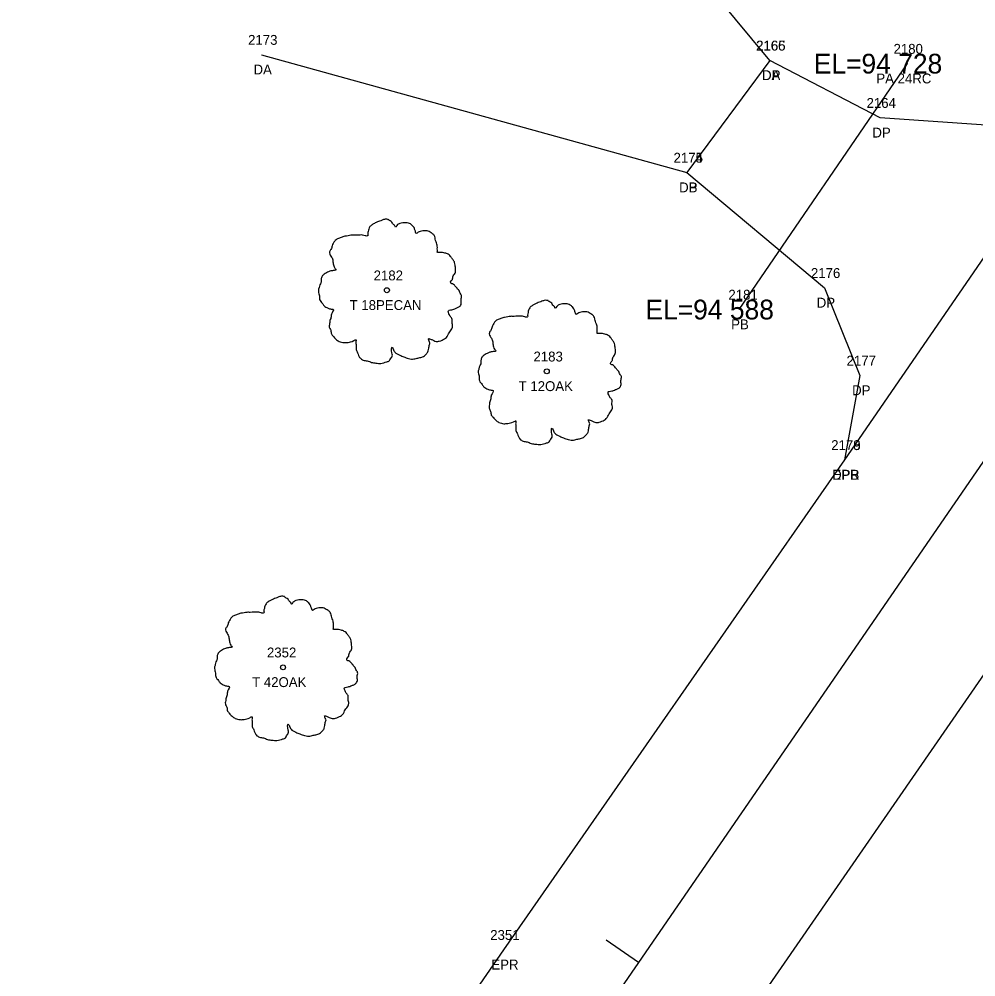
# Model space of a CAD drawing. Extents: x 2266664 to 2272542, y 716533 to 724777.
# Drawn here: x 2271769.3 to 2271866.2, y 723993.3 to 724090.3 of the extents above; entities that cross this region are included whole.
import ezdxf

# ---------------------------------------------------------------- set-up
doc = ezdxf.new("R2010")
doc.units = 0
for name, color, linetype in [('RD_EX_DR_Pipe', 7, 'Continuous'), ('RD_EX_DR_Pipe_txCode', 7, 'Continuous'), ('RD_EX_Driveway', 7, 'Continuous'), ('RD_EX_Driveway_txCode', 7, 'Continuous'), ('RD_EX_Road', 7, 'Continuous'), ('RD_EX_Road_txCode', 7, 'Continuous'), ('RD_EX_VEG', 7, 'Continuous'), ('RD_EX_VEG_txCode', 7, 'Continuous'), ('RD_HC_Cl', 7, 'Continuous'), ('RD_HC_Data_Tic', 7, 'Continuous'), ('RD_SMD_Locator', 7, 'Continuous'), ('RD_TX_Pipe_ElevEX', 7, 'Continuous')]:
    doc.layers.add(name, color=color, linetype=linetype)

msp = doc.modelspace()

# ---------------------------------------------------------------- linework, layer by layer
at = {"layer": 'RD_EX_DR_Pipe'}
msp.add_line((2271859.252, 724085.767), (2271842.205, 724060.863), dxfattribs=at)
at = {"layer": 'RD_EX_Driveway'}
for p, q in [((2271845.335, 724086.097), (2271819.867, 724116.758)), ((2271793.852, 724086.675), (2271836.935, 724074.737))]:
    msp.add_line(p, q, dxfattribs=at)
msp.add_lwpolyline([(2271879.395, 724084.162), (2271867.735, 724079.491), (2271856.504, 724080.286), (2271845.335, 724086.097), (2271836.935, 724074.737), (2271850.87, 724063.059), (2271854.455, 724054.184), (2271852.899, 724045.631)], dxfattribs=at)
at = {"layer": 'RD_EX_Road'}
for points in [[(2272350.524, 724770.05), (2272301.752, 724698.898), (2272265.201, 724646.018), (2272253.016, 724627.92), (2272200.511, 724550.874), (2272147.542, 724474.345), (2272126.282, 724443.661), (2272107.363, 724416.481), (2272092.202, 724393.687), (2272038.416, 724315.204), (2271991.524, 724247.474), (2271974.411, 724222.156), (2271928.733, 724155.869), (2271879.395, 724084.162), (2271852.899, 724045.631), (2271818.371, 723996.017), (2271765.116, 723918.771), (2271712.349, 723841.582), (2271659.046, 723763.608), (2271604.53, 723684.774), (2271550.651, 723606.609)], [(2272368.973, 724754.134), (2272346.573, 724721.921), (2272321.774, 724685.095), (2272273.252, 724614.425), (2272223.015, 724540.912), (2272206.831, 724517.638), (2272178.601, 724477.026), (2272166.485, 724459.37), (2272137.666, 724416.893), (2272108.529, 724374.933), (2272057.894, 724300.992), (2272036.237, 724269.85), (2272022.133, 724249.172), (2272003.164, 724221.268), (2271948.474, 724142.381), (2271900.702, 724072.985), (2271873.703, 724033.584), (2271837.938, 723981.874), (2271784.957, 723904.948), (2271732.121, 723828.062), (2271678.324, 723749.568), (2271627.924, 723676.616), (2271614.207, 723655.348), (2271570.616, 723593.072)]]:
    msp.add_lwpolyline(points, dxfattribs=at)
at = {"layer": 'RD_EX_VEG'}
for centre, radius in [((2271806.565, 724062.817), 0.25), ((2271806.552, 724062.798), 0.0001), ((2271822.751, 724054.604), 0.25), ((2271822.739, 724054.586), 0.0001), ((2271796.045, 724024.628), 0.25), ((2271796.032, 724024.609), 0.0001)]:
    msp.add_circle(centre, radius, dxfattribs=at)
for points in [[(2271806.697, 724069.984), (2271806.397, 724070.009), (2271806.072, 724069.909), (2271805.822, 724069.809), (2271805.597, 724069.734), (2271805.373, 724069.634), (2271805.073, 724069.459), (2271804.848, 724069.259), (2271804.723, 724069.009), (2271804.673, 724068.784), (2271804.623, 724068.51), (2271804.623, 724068.335), (2271804.498, 724068.31), (2271804.348, 724068.335), (2271804.098, 724068.41), (2271803.848, 724068.41), (2271803.598, 724068.41), (2271803.248, 724068.385), (2271802.899, 724068.385), (2271802.624, 724068.335), (2271802.299, 724068.285), (2271801.924, 724068.16), (2271801.574, 724068.035), (2271801.274, 724067.785), (2271801.024, 724067.31), (2271800.899, 724066.96), (2271800.75, 724066.71), (2271800.899, 724066.261), (2271801.074, 724065.911), (2271801.099, 724065.711), (2271801.174, 724065.286), (2271801.274, 724065.061), (2271801.399, 724064.861), (2271801.324, 724064.836), (2271800.949, 724064.786), (2271800.65, 724064.686), (2271800.225, 724064.461), (2271800, 724064.236), (2271799.9, 724063.912), (2271799.875, 724063.562), (2271799.775, 724063.362), (2271799.7, 724063.087), (2271799.675, 724063.012), (2271799.625, 724062.687), (2271799.725, 724062.237), (2271799.75, 724061.887), (2271799.875, 724061.663), (2271800.025, 724061.488), (2271800.2, 724061.238), (2271800.6, 724061.013), (2271800.924, 724060.913), (2271801.124, 724060.888), (2271800.949, 724060.388), (2271800.899, 724060.038), (2271800.775, 724059.638), (2271800.775, 724059.564), (2271800.725, 724059.089), (2271800.874, 724058.764), (2271800.949, 724058.389), (2271801.124, 724058.164), (2271801.399, 724057.864), (2271801.724, 724057.639), (2271802.224, 724057.514), (2271802.624, 724057.539), (2271803.199, 724057.714), (2271803.448, 724057.789), (2271803.423, 724057.614), (2271803.448, 724057.239), (2271803.448, 724056.815), (2271803.598, 724056.49), (2271803.698, 724056.215), (2271803.848, 724055.965), (2271804.173, 724055.74), (2271804.573, 724055.665), (2271804.998, 724055.515), (2271805.448, 724055.44), (2271805.947, 724055.415), (2271806.547, 724055.565), (2271806.822, 724055.69), (2271806.922, 724055.865), (2271807.122, 724056.24), (2271807.072, 724056.465), (2271807.097, 724057.065), (2271807.197, 724056.89), (2271807.372, 724056.54), (2271807.871, 724056.24), (2271808.271, 724056.065), (2271808.746, 724055.915), (2271809.046, 724055.84), (2271809.521, 724055.915), (2271809.896, 724055.99), (2271810.27, 724056.115), (2271810.57, 724056.39), (2271810.745, 724056.665), (2271810.795, 724056.94), (2271810.87, 724057.314), (2271810.92, 724057.489)], [(2271810.92, 724057.489), (2271810.845, 724057.664), (2271810.795, 724057.914), (2271810.87, 724057.889), (2271811.045, 724057.839), (2271811.32, 724057.714), (2271811.545, 724057.639), (2271811.87, 724057.664), (2271812.145, 724057.764), (2271812.594, 724058.039), (2271812.869, 724058.514), (2271813.144, 724058.914), (2271813.219, 724059.239), (2271813.169, 724059.464), (2271813.144, 724059.963), (2271812.944, 724060.213), (2271812.894, 724060.338), (2271812.794, 724060.738), (2271812.869, 724060.788), (2271813.144, 724060.838), (2271813.519, 724060.963), (2271813.794, 724061.088), (2271814.019, 724061.263), (2271814.094, 724061.488), (2271814.069, 724061.887), (2271814.119, 724062.287), (2271814.044, 724062.437), (2271813.944, 724062.587), (2271813.869, 724062.787), (2271813.719, 724062.937), (2271813.619, 724063.087), (2271813.519, 724063.187), (2271813.394, 724063.337), (2271813.219, 724063.462), (2271813.069, 724063.512), (2271813.019, 724063.662), (2271813.169, 724063.862), (2271813.219, 724063.962), (2271813.244, 724064.186), (2271813.469, 724064.536), (2271813.519, 724064.936), (2271813.469, 724065.361), (2271813.419, 724065.636), (2271813.269, 724065.911), (2271813.069, 724066.161), (2271812.944, 724066.336), (2271812.769, 724066.46), (2271812.444, 724066.585), (2271812.195, 724066.635), (2271811.845, 724066.635), (2271811.645, 724066.685), (2271811.67, 724066.735), (2271811.67, 724066.885), (2271811.67, 724067.16), (2271811.595, 724067.61), (2271811.445, 724068.11), (2271811.445, 724068.135), (2271811.345, 724068.385), (2271811.12, 724068.585), (2271810.945, 724068.684), (2271810.745, 724068.809), (2271810.495, 724068.834), (2271810.195, 724068.834), (2271809.921, 724068.784), (2271809.721, 724068.684), (2271809.546, 724068.56), (2271809.471, 724068.709), (2271809.371, 724069.009), (2271809.321, 724069.159), (2271809.171, 724069.334), (2271808.946, 724069.534), (2271808.496, 724069.659), (2271807.871, 724069.584), (2271807.572, 724069.384), (2271807.422, 724069.209), (2271807.372, 724069.334), (2271807.172, 724069.534), (2271807.072, 724069.709), (2271806.897, 724069.834), (2271806.747, 724069.934), (2271806.647, 724069.984)], [(2271822.883, 724061.772), (2271822.583, 724061.797), (2271822.259, 724061.697), (2271822.009, 724061.597), (2271821.784, 724061.522), (2271821.559, 724061.422), (2271821.259, 724061.247), (2271821.034, 724061.047), (2271820.909, 724060.797), (2271820.859, 724060.572), (2271820.809, 724060.297), (2271820.809, 724060.122), (2271820.684, 724060.097), (2271820.534, 724060.122), (2271820.284, 724060.197), (2271820.035, 724060.197), (2271819.785, 724060.197), (2271819.435, 724060.172), (2271819.085, 724060.172), (2271818.81, 724060.122), (2271818.485, 724060.072), (2271818.11, 724059.947), (2271817.761, 724059.822), (2271817.461, 724059.573), (2271817.211, 724059.098), (2271817.086, 724058.748), (2271816.936, 724058.498), (2271817.086, 724058.048), (2271817.261, 724057.698), (2271817.286, 724057.498), (2271817.361, 724057.074), (2271817.461, 724056.849), (2271817.586, 724056.649), (2271817.511, 724056.624), (2271817.136, 724056.574), (2271816.836, 724056.474), (2271816.411, 724056.249), (2271816.186, 724056.024), (2271816.086, 724055.699), (2271816.061, 724055.349), (2271815.961, 724055.15), (2271815.886, 724054.875), (2271815.861, 724054.8), (2271815.811, 724054.475), (2271815.911, 724054.025), (2271815.936, 724053.675), (2271816.061, 724053.45), (2271816.211, 724053.275), (2271816.386, 724053.025), (2271816.786, 724052.801), (2271817.111, 724052.701), (2271817.311, 724052.676), (2271817.136, 724052.176), (2271817.086, 724051.826), (2271816.961, 724051.426), (2271816.961, 724051.351), (2271816.911, 724050.876), (2271817.061, 724050.551), (2271817.136, 724050.177), (2271817.311, 724049.952), (2271817.586, 724049.652), (2271817.91, 724049.427), (2271818.41, 724049.302), (2271818.81, 724049.327), (2271819.385, 724049.502), (2271819.635, 724049.577), (2271819.61, 724049.402), (2271819.635, 724049.027), (2271819.635, 724048.602), (2271819.785, 724048.278), (2271819.885, 724048.003), (2271820.035, 724047.753), (2271820.359, 724047.528), (2271820.759, 724047.453), (2271821.184, 724047.303), (2271821.634, 724047.228), (2271822.134, 724047.203), (2271822.733, 724047.353), (2271823.008, 724047.478), (2271823.108, 724047.653), (2271823.308, 724048.028), (2271823.258, 724048.253), (2271823.283, 724048.852), (2271823.383, 724048.677), (2271823.558, 724048.327), (2271824.058, 724048.028), (2271824.458, 724047.853), (2271824.932, 724047.703), (2271825.232, 724047.628), (2271825.707, 724047.703), (2271826.082, 724047.778), (2271826.457, 724047.903), (2271826.757, 724048.178), (2271826.932, 724048.452), (2271826.982, 724048.727), (2271827.056, 724049.102), (2271827.106, 724049.277)], [(2271827.106, 724049.277), (2271827.032, 724049.452), (2271826.982, 724049.702), (2271827.056, 724049.677), (2271827.231, 724049.627), (2271827.506, 724049.502), (2271827.731, 724049.427), (2271828.056, 724049.452), (2271828.331, 724049.552), (2271828.781, 724049.827), (2271829.056, 724050.302), (2271829.33, 724050.701), (2271829.405, 724051.026), (2271829.355, 724051.251), (2271829.33, 724051.751), (2271829.131, 724052.001), (2271829.081, 724052.126), (2271828.981, 724052.526), (2271829.056, 724052.576), (2271829.33, 724052.626), (2271829.705, 724052.751), (2271829.98, 724052.875), (2271830.205, 724053.05), (2271830.28, 724053.275), (2271830.255, 724053.675), (2271830.305, 724054.075), (2271830.23, 724054.225), (2271830.13, 724054.375), (2271830.055, 724054.575), (2271829.905, 724054.725), (2271829.805, 724054.875), (2271829.705, 724054.975), (2271829.58, 724055.125), (2271829.405, 724055.249), (2271829.256, 724055.299), (2271829.206, 724055.449), (2271829.355, 724055.649), (2271829.405, 724055.749), (2271829.43, 724055.974), (2271829.655, 724056.324), (2271829.705, 724056.724), (2271829.655, 724057.149), (2271829.605, 724057.424), (2271829.455, 724057.698), (2271829.256, 724057.948), (2271829.131, 724058.123), (2271828.956, 724058.248), (2271828.631, 724058.373), (2271828.381, 724058.423), (2271828.031, 724058.423), (2271827.831, 724058.473), (2271827.856, 724058.523), (2271827.856, 724058.673), (2271827.856, 724058.948), (2271827.781, 724059.398), (2271827.631, 724059.897), (2271827.631, 724059.922), (2271827.531, 724060.172), (2271827.306, 724060.372), (2271827.131, 724060.472), (2271826.932, 724060.597), (2271826.682, 724060.622), (2271826.382, 724060.622), (2271826.107, 724060.572), (2271825.907, 724060.472), (2271825.732, 724060.347), (2271825.657, 724060.497), (2271825.557, 724060.797), (2271825.507, 724060.947), (2271825.357, 724061.122), (2271825.132, 724061.322), (2271824.682, 724061.447), (2271824.058, 724061.372), (2271823.758, 724061.172), (2271823.608, 724060.997), (2271823.558, 724061.122), (2271823.358, 724061.322), (2271823.258, 724061.497), (2271823.083, 724061.622), (2271822.933, 724061.722), (2271822.833, 724061.772)], [(2271796.177, 724031.795), (2271795.877, 724031.82), (2271795.552, 724031.72), (2271795.302, 724031.62), (2271795.077, 724031.545), (2271794.852, 724031.445), (2271794.552, 724031.27), (2271794.327, 724031.07), (2271794.202, 724030.82), (2271794.152, 724030.595), (2271794.102, 724030.32), (2271794.102, 724030.145), (2271793.978, 724030.12), (2271793.828, 724030.145), (2271793.578, 724030.22), (2271793.328, 724030.22), (2271793.078, 724030.22), (2271792.728, 724030.195), (2271792.378, 724030.195), (2271792.103, 724030.145), (2271791.778, 724030.096), (2271791.404, 724029.971), (2271791.054, 724029.846), (2271790.754, 724029.596), (2271790.504, 724029.121), (2271790.379, 724028.771), (2271790.229, 724028.521), (2271790.379, 724028.071), (2271790.554, 724027.722), (2271790.579, 724027.522), (2271790.654, 724027.097), (2271790.754, 724026.872), (2271790.879, 724026.672), (2271790.804, 724026.647), (2271790.429, 724026.597), (2271790.129, 724026.497), (2271789.704, 724026.272), (2271789.479, 724026.047), (2271789.379, 724025.722), (2271789.355, 724025.373), (2271789.255, 724025.173), (2271789.18, 724024.898), (2271789.155, 724024.823), (2271789.105, 724024.498), (2271789.205, 724024.048), (2271789.23, 724023.698), (2271789.355, 724023.473), (2271789.504, 724023.299), (2271789.679, 724023.049), (2271790.079, 724022.824), (2271790.404, 724022.724), (2271790.604, 724022.699), (2271790.429, 724022.199), (2271790.379, 724021.849), (2271790.254, 724021.449), (2271790.254, 724021.374), (2271790.204, 724020.9), (2271790.354, 724020.575), (2271790.429, 724020.2), (2271790.604, 724019.975), (2271790.879, 724019.675), (2271791.204, 724019.45), (2271791.704, 724019.325), (2271792.103, 724019.35), (2271792.678, 724019.525), (2271792.928, 724019.6), (2271792.903, 724019.425), (2271792.928, 724019.05), (2271792.928, 724018.626), (2271793.078, 724018.301), (2271793.178, 724018.026), (2271793.328, 724017.776), (2271793.653, 724017.551), (2271794.052, 724017.476), (2271794.477, 724017.326), (2271794.927, 724017.251), (2271795.427, 724017.226), (2271796.027, 724017.376), (2271796.301, 724017.501), (2271796.401, 724017.676), (2271796.601, 724018.051), (2271796.551, 724018.276), (2271796.576, 724018.875), (2271796.676, 724018.7), (2271796.851, 724018.351), (2271797.351, 724018.051), (2271797.751, 724017.876), (2271798.226, 724017.726), (2271798.526, 724017.651), (2271799, 724017.726), (2271799.375, 724017.801), (2271799.75, 724017.926), (2271800.05, 724018.201), (2271800.225, 724018.476), (2271800.275, 724018.75), (2271800.35, 724019.125), (2271800.4, 724019.3)], [(2271800.4, 724019.3), (2271800.325, 724019.475), (2271800.275, 724019.725), (2271800.35, 724019.7), (2271800.525, 724019.65), (2271800.8, 724019.525), (2271801.024, 724019.45), (2271801.349, 724019.475), (2271801.624, 724019.575), (2271802.074, 724019.85), (2271802.349, 724020.325), (2271802.624, 724020.725), (2271802.699, 724021.049), (2271802.649, 724021.274), (2271802.624, 724021.774), (2271802.424, 724022.024), (2271802.374, 724022.149), (2271802.274, 724022.549), (2271802.349, 724022.599), (2271802.624, 724022.649), (2271802.999, 724022.774), (2271803.273, 724022.899), (2271803.498, 724023.074), (2271803.573, 724023.299), (2271803.548, 724023.698), (2271803.598, 724024.098), (2271803.523, 724024.248), (2271803.423, 724024.398), (2271803.348, 724024.598), (2271803.198, 724024.748), (2271803.099, 724024.898), (2271802.999, 724024.998), (2271802.874, 724025.148), (2271802.699, 724025.273), (2271802.549, 724025.323), (2271802.499, 724025.473), (2271802.649, 724025.672), (2271802.699, 724025.772), (2271802.724, 724025.997), (2271802.949, 724026.347), (2271802.999, 724026.747), (2271802.949, 724027.172), (2271802.899, 724027.447), (2271802.749, 724027.722), (2271802.549, 724027.971), (2271802.424, 724028.146), (2271802.249, 724028.271), (2271801.924, 724028.396), (2271801.674, 724028.446), (2271801.324, 724028.446), (2271801.124, 724028.496), (2271801.149, 724028.546), (2271801.149, 724028.696), (2271801.149, 724028.971), (2271801.074, 724029.421), (2271800.924, 724029.921), (2271800.924, 724029.946), (2271800.824, 724030.195), (2271800.6, 724030.395), (2271800.425, 724030.495), (2271800.225, 724030.62), (2271799.975, 724030.645), (2271799.675, 724030.645), (2271799.4, 724030.595), (2271799.2, 724030.495), (2271799.025, 724030.37), (2271798.95, 724030.52), (2271798.85, 724030.82), (2271798.8, 724030.97), (2271798.65, 724031.145), (2271798.426, 724031.345), (2271797.976, 724031.47), (2271797.351, 724031.395), (2271797.051, 724031.195), (2271796.901, 724031.02), (2271796.851, 724031.145), (2271796.651, 724031.345), (2271796.551, 724031.52), (2271796.376, 724031.645), (2271796.227, 724031.745), (2271796.127, 724031.795)]]:
    msp.add_spline(points, degree=3, dxfattribs=at)
at = {"layer": 'RD_HC_Cl'}
msp.add_line((2267342.915, 717471.203), (2272360.46, 724762.595), dxfattribs=at)
at = {"layer": 'RD_HC_Data_Tic'}
msp.add_line((2271832.053, 723994.725), (2271828.758, 723996.993), dxfattribs=at)
at = {"layer": 'RD_SMD_Locator'}
for centre in [(2271793.852, 724086.675), (2271845.335, 724086.097), (2271845.335, 724086.097), (2271859.252, 724085.767), (2271856.504, 724080.286), (2271836.935, 724074.737), (2271836.935, 724074.737), (2271850.87, 724063.059), (2271842.205, 724060.863), (2271854.455, 724054.184), (2271852.899, 724045.631), (2271852.899, 724045.631), (2271818.371, 723996.017)]:
    msp.add_circle(centre, 0.001, dxfattribs=at)

# ---------------------------------------------------------------- texts
at = {"layer": 'RD_EX_DR_Pipe_txCode'}
for s, p in [('2180', (2271857.866, 724086.767)), ('PA 24RC', (2271856.126, 724083.767)), ('2181', (2271841.142, 724061.863)), ('PB', (2271841.426, 724058.863))]:
    msp.add_text(s, height=1, dxfattribs=at).set_placement(p)
at = {"layer": 'RD_EX_Driveway_txCode'}
for s, p in [('2173', (2271792.505, 724087.675)), ('2166', (2271843.941, 724087.097)), ('2165', (2271843.965, 724087.097)), ('DA', (2271793.056, 724084.675)), ('DA', (2271844.54, 724084.097)), ('DP', (2271844.555, 724084.097)), ('2164', (2271855.134, 724081.286)), ('DP', (2271855.724, 724078.286)), ('2174', (2271835.588, 724075.737)), ('2175', (2271835.588, 724075.737)), ('DB', (2271836.155, 724072.737)), ('DP', (2271836.155, 724072.737)), ('2176', (2271849.5, 724064.059)), ('DP', (2271850.09, 724061.059)), ('2177', (2271853.108, 724055.184)), ('DP', (2271853.675, 724052.184)), ('2178', (2271851.553, 724046.631)), ('DPB', (2271851.648, 724043.631))]:
    msp.add_text(s, height=1, dxfattribs=at).set_placement(p)
at = {"layer": 'RD_EX_Road_txCode'}
for s, p in [('2179', (2271851.553, 724046.631)), ('EPR', (2271851.671, 724043.631)), ('2351', (2271817.025, 723997.017)), ('EPR', (2271817.143, 723994.017))]:
    msp.add_text(s, height=1, dxfattribs=at).set_placement(p)
at = {"layer": 'RD_EX_VEG_txCode'}
for s, p in [('2182', (2271805.219, 724063.817)), ('T 18PECAN', (2271802.785, 724060.817)), ('2183', (2271821.405, 724055.604)), ('T 12OAK', (2271819.901, 724052.604)), ('2352', (2271794.415, 724025.628)), ('T 42OAK', (2271792.911, 724022.628))]:
    msp.add_text(s, height=1, dxfattribs=at).set_placement(p)
at = {"layer": 'RD_TX_Pipe_ElevEX'}
for s, p in [('EL=94 728  ', (2271849.787, 724084.767)), ('EL=94 588  ', (2271832.741, 724059.863))]:
    msp.add_text(s, height=2, dxfattribs=at).set_placement(p)

doc.saveas('drawing.dxf')
